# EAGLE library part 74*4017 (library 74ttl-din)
4-bit asynchronous decade COUNTER
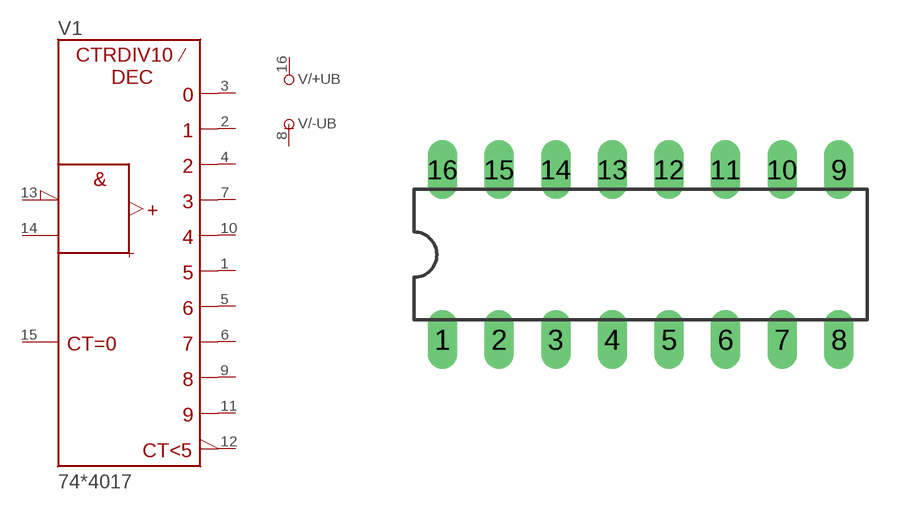
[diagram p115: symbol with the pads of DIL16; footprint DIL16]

Designator prefix V; gates /+UB=+UB /-UB=-UB 1=4017

## 744017N  [DIL16]
1  1:Y5  out
2  1:Y1  out
3  1:Y0  out
4  1:Y2  out
5  1:Y6  out
6  1:Y7  out
7  1:Y3  out
8  /-UB:-UB  pwr
9  1:Y8  out
10  1:Y4  out
11  1:Y9  out
12  1:CO  out
13  1:CLKEN\  in
14  1:CLK  in
15  1:CLR  in
16  /+UB:+UB  pwr

## Footprint DIL16 (pad centres in mm)
Dual In Line Package
drill 0.813 long: 1 -8.89,-3.81; 2 -6.35,-3.81; 3 -3.81,-3.81; 4 -1.27,-3.81; 5 1.27,-3.81; 6 3.81,-3.81; 7 6.35,-3.81; 8 8.89,-3.81; 9 8.89,3.81; 10 6.35,3.81; 11 3.81,3.81; 12 1.27,3.81; 13 -1.27,3.81; 14 -3.81,3.81; 15 -6.35,3.81; 16 -8.89,3.81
